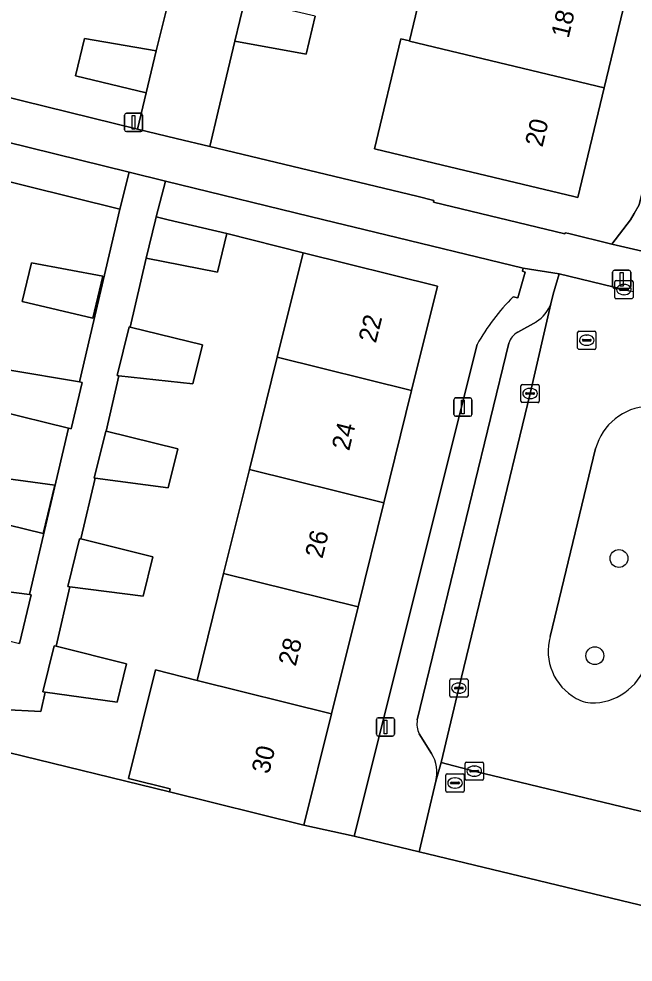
# Model space of a CAD drawing. Extents: x 162803 to 163818, y 381639 to 382475.
# Drawn here: x 163103.1 to 163136.7, y 382209.4 to 382261 of the extents above; entities that cross this region are included whole.
import ezdxf

# ---------------------------------------------------------------- set-up
doc = ezdxf.new("R2010")
doc.units = 0
for name, color, linetype in [('IMGEO_Boom', 7, 'Continuous'), ('IMGEO_Erf', 7, 'Continuous'), ('IMGEO_Groenvoorziening', 7, 'Continuous'), ('IMGEO_Hek', 7, 'Continuous'), ('IMGEO_Kolk', 7, 'Continuous'), ('IMGEO_Lichtmast', 7, 'Continuous'), ('IMGEO_Pand', 7, 'Continuous'), ('IMGEO_Pand_nummerreeks', 7, 'Continuous'), ('IMGEO_Parkeervlak_open', 7, 'Continuous'), ('IMGEO_Rijbaan_lokaal_open', 7, 'Continuous'), ('IMGEO_Rioolput', 7, 'Continuous'), ('IMGEO_Voetpad_open', 7, 'Continuous')]:
    doc.layers.add(name, color=color, linetype=linetype)

msp = doc.modelspace()

# ---------------------------------------------------------------- linework, layer by layer
at = {"layer": 'IMGEO_Boom'}
for centre in [(163135.913, 382231.467), (163134.592, 382226.148)]:
    msp.add_circle(centre, 0.489, dxfattribs=at)
at = {"layer": 'IMGEO_Erf'}
for points in [[(163119.287, 382261.142), (163118.793, 382259.063), (163114.901, 382259.759), (163113.984, 382255.944), (163113.517, 382254.008), (163124.858, 382251.282), (163125.788, 382251.054), (163125.763, 382250.951), (163132.954, 382249.227), (163132.969, 382249.291), (163133.177, 382249.24), (163135.523, 382248.664), (163136.536, 382250), (163136.747, 382250.336), (163137.011, 382250.814), (163151.17, 382309.066)], [(163136.518, 382263.116), (163135.102, 382257.214), (163133.662, 382251.208), (163133.442, 382251.261), (163126.251, 382252.986), (163122.54, 382253.876), (163123.982, 382259.89), (163124.451, 382259.778), (163125.844, 382265.582)], [(163090.662, 382259.598), (163109.57, 382254.957), (163110.032, 382256.941), (163106.177, 382257.866), (163106.669, 382259.919), (163110.582, 382259.234), (163111.502, 382262.908)], [(163102.463, 382241.778), (163106.389, 382241.125), (163108.604, 382250.569), (163100.863, 382252.485)], [(163130.126, 382245.787), (163130.388, 382245.731), (163130.783, 382247.133), (163130.637, 382247.179), (163130.671, 382247.351), (163122.549, 382249.324), (163119.771, 382250), (163111.102, 382252.11), (163110.582, 382250.157), (163111.242, 382250), (163114.449, 382249.237), (163118.626, 382248.182), (163125.984, 382246.357), (163124.569, 382240.655), (163123.046, 382234.515), (163121.633, 382228.819), (163120.183, 382222.974), (163118.671, 382216.877), (163121.429, 382216.275), (163128.151, 382243.17)], [(163093.672, 382223), (163111.314, 382218.702), (163111.353, 382218.859), (163109.073, 382219.425), (163110.546, 382225.365), (163112.826, 382224.799), (163114.276, 382230.644), (163115.689, 382236.341), (163117.212, 382242.481), (163118.626, 382248.182), (163114.449, 382249.237), (163113.948, 382247.127), (163110.043, 382247.894), (163109.168, 382244.13), (163113.115, 382243.151), (163112.586, 382241.016), (163108.548, 382241.464), (163107.843, 382238.433), (163111.768, 382237.46), (163111.239, 382235.329), (163107.244, 382235.858), (163106.471, 382232.532), (163110.405, 382231.555), (163109.87, 382229.401), (163105.862, 382229.913), (163105.106, 382226.662), (163108.968, 382225.704), (163108.448, 382223.605), (163104.522, 382224.152), (163104.275, 382223.089), (163102.186, 382223.204)], [(163099.653, 382229.998), (163103.66, 382229.49), (163105.796, 382238.598), (163101.918, 382239.544)]]:
    msp.add_lwpolyline(points, dxfattribs=at)
for points in [[(163089.618, 382255.32), (163093.508, 382254.28), (163100.863, 382252.485), (163108.604, 382250.569), (163109.113, 382252.594), (163090.093, 382257.281)], [(163107.115, 382244.612), (163103.258, 382245.529), (163103.761, 382247.643), (163107.663, 382246.92)], [(163101.14, 382236.002), (163105.049, 382235.468), (163104.406, 382232.828), (163100.593, 382233.758)], [(163150.047, 382209.293), (163144.013, 382210.786), (163141.809, 382211.34), (163138.535, 382212.15), (163124.973, 382215.424), (163121.429, 382216.275), (163118.671, 382216.877), (163111.314, 382218.702), (163093.672, 382223), (163086.358, 382224.789), (163082.453, 382225.745), (163069.123, 382170.722), (163071.74, 382166.782), (163081.213, 382162.978), (163089.555, 382160.344), (163135.606, 382149.117)]]:
    msp.add_lwpolyline(points, close=True, dxfattribs=at)
msp.add_arc((163138.783, 382237.2), 12.193, 135.2324, 150.6853, dxfattribs=at)
at = {"layer": 'IMGEO_Groenvoorziening'}
msp.add_lwpolyline([(163134.638, 382237.481), (163132.148, 382227.198)], dxfattribs=at)
for centre, radius, start, end in [((163137.644, 382236.677), 3.112, 92.1882, 165.0199), ((163134.995, 382226.402), 2.956, 164.378, 241.2288), ((163134.437, 382226.69), 3.125, 273.367, 345.671), ((163134.471, 382225.329), 1.764, 239.3539, 274.8724)]:
    msp.add_arc(centre, radius, start, end, dxfattribs=at)
at = {"layer": 'IMGEO_Hek'}
for points in [[(163109.57, 382254.957), (163111.675, 382254.451)], [(163118.671, 382216.877), (163121.429, 382216.275)]]:
    msp.add_lwpolyline(points, dxfattribs=at)
at = {"layer": 'IMGEO_Kolk'}
for p, q in [((163135.683, 382245.751), (163135.683, 382246.603)), ((163135.758, 382246.677), (163136.61, 382246.677)), ((163136.171, 382246.457), (163136.196, 382246.457)), ((163136.684, 382246.603), (163136.684, 382245.751)), ((163135.942, 382246.171), (163135.942, 382246.183)), ((163136.38, 382246.134), (163135.982, 382246.134)), ((163135.985, 382246.22), (163136.383, 382246.22)), ((163136.194, 382245.897), (163136.169, 382245.897)), ((163136.426, 382246.183), (163136.426, 382246.171)), ((163136.61, 382245.677), (163135.758, 382245.677)), ((163130.548, 382240.065), (163130.548, 382240.917)), ((163130.623, 382240.991), (163131.475, 382240.991)), ((163131.036, 382240.771), (163131.061, 382240.771)), ((163131.549, 382240.917), (163131.549, 382240.065)), ((163130.807, 382240.485), (163130.807, 382240.497)), ((163131.245, 382240.448), (163130.847, 382240.448)), ((163130.85, 382240.534), (163131.248, 382240.534)), ((163131.059, 382240.211), (163131.034, 382240.211)), ((163131.291, 382240.497), (163131.291, 382240.485)), ((163131.475, 382239.991), (163130.623, 382239.991)), ((163126.652, 382223.948), (163126.652, 382224.8)), ((163126.727, 382224.874), (163127.579, 382224.874)), ((163127.653, 382224.8), (163127.653, 382223.948)), ((163126.911, 382224.368), (163126.911, 382224.38)), ((163127.349, 382224.331), (163126.951, 382224.331)), ((163126.954, 382224.417), (163127.352, 382224.417)), ((163127.14, 382224.654), (163127.165, 382224.654)), ((163127.395, 382224.38), (163127.395, 382224.368)), ((163127.579, 382223.874), (163126.727, 382223.874)), ((163127.163, 382224.094), (163127.138, 382224.094)), ((163127.495, 382219.405), (163127.495, 382220.257)), ((163127.57, 382220.331), (163128.422, 382220.331)), ((163127.983, 382220.111), (163128.008, 382220.111)), ((163128.496, 382220.257), (163128.496, 382219.405)), ((163127.754, 382219.825), (163127.754, 382219.837)), ((163128.192, 382219.788), (163127.794, 382219.788)), ((163127.797, 382219.874), (163128.195, 382219.874)), ((163128.006, 382219.551), (163127.981, 382219.551)), ((163128.238, 382219.837), (163128.238, 382219.825)), ((163128.422, 382219.331), (163127.57, 382219.331))]:
    msp.add_line(p, q, dxfattribs=at)
for points in [[(163135.683, 382245.751), (163135.683, 382246.603)], [(163135.758, 382246.677), (163136.61, 382246.677)], [(163136.684, 382246.603), (163136.684, 382245.751)], [(163136.61, 382245.677), (163135.758, 382245.677)], [(163130.548, 382240.065), (163130.548, 382240.917)], [(163130.623, 382240.991), (163131.475, 382240.991)], [(163131.549, 382240.917), (163131.549, 382240.065)], [(163131.475, 382239.991), (163130.623, 382239.991)], [(163126.652, 382223.948), (163126.652, 382224.8)], [(163126.727, 382224.874), (163127.579, 382224.874)], [(163127.653, 382224.8), (163127.653, 382223.948)], [(163127.579, 382223.874), (163126.727, 382223.874)], [(163127.495, 382219.405), (163127.495, 382220.257)], [(163127.57, 382220.331), (163128.422, 382220.331)], [(163128.496, 382220.257), (163128.496, 382219.405)], [(163128.422, 382219.331), (163127.57, 382219.331)]]:
    msp.add_lwpolyline(points, dxfattribs=at)
for centre, radius, start, end in [((163135.76, 382246.601), 0.0765, 91.552, 178.448), ((163135.76, 382246.601), 0.0765, 91.552, 178.448), ((163136.608, 382246.601), 0.0765, 1.552, 88.448), ((163136.608, 382246.601), 0.0765, 1.552, 88.448), ((163135.982, 382246.18), 0.0403, 85.8775, 175.7526), ((163135.979, 382246.17), 0.0366, 178.938, 274.7102), ((163136.383, 382246.177), 0.043, 264.8664, 352.4533), ((163136.387, 382246.182), 0.0386, 1.7309, 96.639), ((163135.76, 382245.753), 0.0765, 181.552, 268.448), ((163135.76, 382245.753), 0.0765, 181.552, 268.448), ((163136.608, 382245.753), 0.0765, 271.552, 358.448), ((163136.608, 382245.753), 0.0765, 271.552, 358.448), ((163130.625, 382240.915), 0.0765, 91.552, 178.448), ((163130.625, 382240.915), 0.0765, 91.552, 178.448), ((163131.473, 382240.915), 0.0765, 1.552, 88.448), ((163131.473, 382240.915), 0.0765, 1.552, 88.448), ((163130.847, 382240.494), 0.0403, 85.8775, 175.7526), ((163130.844, 382240.484), 0.0366, 178.938, 274.7102), ((163131.248, 382240.491), 0.043, 264.8664, 352.4533), ((163131.252, 382240.496), 0.0386, 1.7309, 96.639), ((163130.625, 382240.067), 0.0765, 181.552, 268.448), ((163130.625, 382240.067), 0.0765, 181.552, 268.448), ((163131.473, 382240.067), 0.0765, 271.552, 358.448), ((163131.473, 382240.067), 0.0765, 271.552, 358.448), ((163126.729, 382224.798), 0.0765, 91.552, 178.448), ((163126.729, 382224.798), 0.0765, 91.552, 178.448), ((163127.577, 382224.798), 0.0765, 1.552, 88.448), ((163127.577, 382224.798), 0.0765, 1.552, 88.448), ((163126.951, 382224.377), 0.0403, 85.8775, 175.7526), ((163126.948, 382224.367), 0.0366, 178.938, 274.7102), ((163127.352, 382224.374), 0.043, 264.8664, 352.4533), ((163127.356, 382224.379), 0.0386, 1.7309, 96.639), ((163126.729, 382223.95), 0.0765, 181.552, 268.448), ((163126.729, 382223.95), 0.0765, 181.552, 268.448), ((163127.577, 382223.95), 0.0765, 271.552, 358.448), ((163127.577, 382223.95), 0.0765, 271.552, 358.448), ((163127.572, 382220.255), 0.0765, 91.552, 178.448), ((163127.572, 382220.255), 0.0765, 91.552, 178.448), ((163128.42, 382220.255), 0.0765, 1.552, 88.448), ((163128.42, 382220.255), 0.0765, 1.552, 88.448), ((163127.794, 382219.834), 0.0403, 85.8775, 175.7526), ((163127.791, 382219.824), 0.0366, 178.938, 274.7102), ((163128.195, 382219.831), 0.043, 264.8664, 352.4533), ((163128.199, 382219.836), 0.0386, 1.7309, 96.639), ((163127.572, 382219.407), 0.0765, 181.552, 268.448), ((163127.572, 382219.407), 0.0765, 181.552, 268.448), ((163128.42, 382219.407), 0.0765, 271.552, 358.448), ((163128.42, 382219.407), 0.0765, 271.552, 358.448)]:
    msp.add_arc(centre, radius, start, end, dxfattribs=at)
for centre, major_axis, ratio, start_param, end_param in [((163136.17, 382246.177), (-0.387, 0.002), 0.722429, 4.712389, 7.853982), ((163136.195, 382246.177), (-0.39, 0.002), 0.717154, 1.570796, 4.712389), ((163131.035, 382240.491), (-0.387, 0.002), 0.722429, 4.712389, 7.853982), ((163131.06, 382240.491), (-0.39, 0.002), 0.717154, 1.570796, 4.712389), ((163127.139, 382224.374), (-0.387, 0.002), 0.722429, 4.712389, 7.853982), ((163127.164, 382224.374), (-0.39, 0.002), 0.717154, 1.570796, 4.712389), ((163127.982, 382219.831), (-0.387, 0.002), 0.722429, 4.712389, 7.853982), ((163128.007, 382219.831), (-0.39, 0.002), 0.717154, 1.570796, 4.712389)]:
    msp.add_ellipse(centre, major_axis=major_axis, ratio=ratio, start_param=start_param, end_param=end_param, dxfattribs=at)
at = {"layer": 'IMGEO_Lichtmast'}
for p, q in [((163108.856, 382254.921), (163108.856, 382255.721)), ((163108.856, 382255.721), (163108.856, 382254.921)), ((163108.956, 382255.821), (163109.746, 382255.821)), ((163109.746, 382255.821), (163108.956, 382255.821)), ((163109.846, 382255.721), (163109.846, 382254.921)), ((163109.846, 382254.921), (163109.846, 382255.721)), ((163109.746, 382254.821), (163108.956, 382254.821)), ((163108.956, 382254.821), (163109.746, 382254.821)), ((163135.565, 382246.337), (163135.565, 382247.137)), ((163135.565, 382247.137), (163135.565, 382246.337)), ((163135.665, 382247.237), (163136.455, 382247.237)), ((163136.455, 382247.237), (163135.665, 382247.237)), ((163136.555, 382247.137), (163136.555, 382246.337)), ((163136.555, 382246.337), (163136.555, 382247.137)), ((163136.455, 382246.237), (163135.665, 382246.237)), ((163135.665, 382246.237), (163136.455, 382246.237)), ((163126.976, 382240.246), (163127.766, 382240.246)), ((163127.766, 382240.246), (163126.976, 382240.246)), ((163126.876, 382239.346), (163126.876, 382240.146)), ((163126.876, 382240.146), (163126.876, 382239.346)), ((163127.866, 382240.146), (163127.866, 382239.346)), ((163127.866, 382239.346), (163127.866, 382240.146)), ((163127.766, 382239.246), (163126.976, 382239.246)), ((163126.976, 382239.246), (163127.766, 382239.246)), ((163122.637, 382221.852), (163122.637, 382222.652)), ((163122.637, 382222.652), (163122.637, 382221.852)), ((163122.737, 382222.752), (163123.527, 382222.752)), ((163123.527, 382222.752), (163122.737, 382222.752)), ((163123.627, 382222.652), (163123.627, 382221.852)), ((163123.627, 382221.852), (163123.627, 382222.652)), ((163123.527, 382221.752), (163122.737, 382221.752)), ((163122.737, 382221.752), (163123.527, 382221.752))]:
    msp.add_line(p, q, dxfattribs=at)
for points in [[(163109.276, 382255.696), (163109.426, 382255.696), (163109.426, 382254.946), (163109.276, 382254.946), (163109.276, 382255.696)], [(163135.985, 382247.112), (163136.135, 382247.112), (163136.135, 382246.362), (163135.985, 382246.362), (163135.985, 382247.112)], [(163127.296, 382240.121), (163127.446, 382240.121), (163127.446, 382239.371), (163127.296, 382239.371), (163127.296, 382240.121)], [(163123.057, 382222.627), (163123.207, 382222.627), (163123.207, 382221.877), (163123.057, 382221.877), (163123.057, 382222.627)]]:
    msp.add_lwpolyline(points, dxfattribs=at)
for centre, start, end in [((163108.956, 382255.721), 90, 180), ((163108.956, 382255.721), 90, 180), ((163109.746, 382255.721), 0, 90), ((163109.746, 382255.721), 360, 90), ((163108.956, 382254.921), 180, 270), ((163108.956, 382254.921), 180, 270), ((163109.746, 382254.921), 270, 0), ((163109.746, 382254.921), 270, 0), ((163135.665, 382247.137), 90, 180), ((163135.665, 382247.137), 90, 180), ((163136.455, 382247.137), 0, 90), ((163136.455, 382247.137), 360, 90), ((163135.665, 382246.337), 180, 270), ((163135.665, 382246.337), 180, 270), ((163136.455, 382246.337), 270, 0), ((163136.455, 382246.337), 270, 0), ((163126.976, 382240.146), 90, 180), ((163126.976, 382240.146), 90, 180), ((163127.766, 382240.146), 0, 90), ((163127.766, 382240.146), 360, 90), ((163126.976, 382239.346), 180, 270), ((163126.976, 382239.346), 180, 270), ((163127.766, 382239.346), 270, 0), ((163127.766, 382239.346), 270, 0), ((163122.737, 382222.652), 90, 180), ((163122.737, 382222.652), 90, 180), ((163123.527, 382222.652), 0, 90), ((163123.527, 382222.652), 360, 90), ((163122.737, 382221.852), 180, 270), ((163122.737, 382221.852), 180, 270), ((163123.527, 382221.852), 270, 0), ((163123.527, 382221.852), 270, 0)]:
    msp.add_arc(centre, 0.1, start, end, dxfattribs=at)
at = {"layer": 'IMGEO_Pand'}
for points in [[(163136.518, 382263.116), (163129.107, 382264.894), (163129.085, 382264.804), (163125.844, 382265.582), (163124.451, 382259.778), (163124.449, 382259.77), (163135.102, 382257.214)], [(163118.793, 382259.063), (163119.287, 382261.142), (163115.447, 382262.055), (163114.901, 382259.759)], [(163110.032, 382256.941), (163110.582, 382259.234), (163106.669, 382259.919), (163106.177, 382257.866)], [(163135.102, 382257.214), (163124.449, 382259.77), (163124.451, 382259.778), (163123.982, 382259.89), (163122.54, 382253.876), (163126.251, 382252.986), (163133.442, 382251.261), (163133.662, 382251.208)], [(163114.449, 382249.237), (163111.242, 382250), (163110.582, 382250.157), (163110.545, 382250), (163110.043, 382247.894), (163113.948, 382247.127)], [(163117.212, 382242.481), (163124.569, 382240.655), (163125.984, 382246.357), (163118.626, 382248.182)], [(163107.115, 382244.612), (163107.663, 382246.92), (163103.761, 382247.643), (163103.258, 382245.529)], [(163109.168, 382244.13), (163109.117, 382244.143), (163108.455, 382241.474), (163108.548, 382241.464), (163112.586, 382241.016), (163113.115, 382243.151)], [(163117.212, 382242.481), (163115.689, 382236.341), (163123.046, 382234.515), (163124.569, 382240.655)], [(163106.389, 382241.125), (163102.463, 382241.778), (163101.918, 382239.544), (163105.796, 382238.598), (163105.928, 382238.566), (163106.546, 382241.099)], [(163107.843, 382238.433), (163107.832, 382238.436), (163107.194, 382235.865), (163107.244, 382235.858), (163111.239, 382235.329), (163111.768, 382237.46)], [(163114.276, 382230.644), (163121.633, 382228.819), (163123.046, 382234.515), (163115.689, 382236.341)], [(163101.14, 382236.002), (163100.593, 382233.758), (163104.406, 382232.828), (163105.049, 382235.468)], [(163106.471, 382232.532), (163106.401, 382232.549), (163105.751, 382229.927), (163105.862, 382229.913), (163109.87, 382229.401), (163110.405, 382231.555)], [(163114.276, 382230.644), (163112.826, 382224.799), (163120.183, 382222.974), (163121.633, 382228.819)], [(163103.66, 382229.49), (163099.653, 382229.998), (163099.115, 382227.792), (163103.038, 382226.835), (163103.1, 382226.82), (163103.748, 382229.479)], [(163105.106, 382226.662), (163105.014, 382226.685), (163104.39, 382224.17), (163104.522, 382224.152), (163108.448, 382223.605), (163108.968, 382225.704)], [(163120.183, 382222.974), (163112.826, 382224.799), (163110.546, 382225.365), (163109.073, 382219.425), (163111.353, 382218.859), (163111.314, 382218.702), (163118.671, 382216.877)]]:
    msp.add_lwpolyline(points, close=True, dxfattribs=at)
at = {"layer": 'IMGEO_Parkeervlak_open'}
for points in [[(163125.897, 382219.282), (163126.177, 382220.3), (163127.154, 382224.374), (163131.05, 382240.49), (163132.188, 382245.406)], [(163131.394, 382244.422), (163130.38, 382243.842)], [(163129.89, 382243.252), (163124.878, 382222.632)], [(163145.726, 382242.413), (163144.32, 382236.804), (163140.443, 382220.841), (163139.498, 382217.076), (163137.595, 382217.507), (163127.997, 382219.832), (163126.177, 382220.3), (163125.897, 382219.282), (163124.973, 382215.424), (163138.535, 382212.15), (163139.43, 382215.984)], [(163124.984, 382221.872), (163125.654, 382220.8)]]:
    msp.add_lwpolyline(points, dxfattribs=at)
for centre, radius, start, end in [((163130.279, 382246.134), 2.043, 303.0758, 339.1234), ((163130.829, 382242.97), 0.98, 117.2659, 163.3143), ((163126.009, 382222.402), 1.154, 168.5294, 207.3507), ((163123.987, 382219.755), 1.968, 346.0997, 32.0897)]:
    msp.add_arc(centre, radius, start, end, dxfattribs=at)
at = {"layer": 'IMGEO_Rijbaan_lokaal_open'}
for points in [[(163136.382, 382246.138), (163136.184, 382246.175), (163132.637, 382247.045), (163132.31, 382245.931), (163132.188, 382245.406), (163131.05, 382240.49), (163127.154, 382224.374), (163126.177, 382220.3), (163127.997, 382219.832), (163137.595, 382217.507), (163139.498, 382217.076), (163140.443, 382220.841), (163144.32, 382236.804), (163145.726, 382242.413)], [(163132.148, 382227.198), (163134.638, 382237.481)]]:
    msp.add_lwpolyline(points, dxfattribs=at)
for centre, radius, start, end in [((163136.919, 382247.993), 1.931, 253.8567, 263.3116), ((163137.644, 382236.677), 3.112, 92.1882, 165.0199), ((163134.995, 382226.402), 2.956, 164.378, 241.2288), ((163134.437, 382226.69), 3.125, 273.367, 345.671), ((163134.471, 382225.329), 1.764, 239.3539, 274.8724)]:
    msp.add_arc(centre, radius, start, end, dxfattribs=at)
at = {"layer": 'IMGEO_Rioolput'}
for p, q in [((163133.65, 382242.981), (163133.65, 382243.833)), ((163133.725, 382243.907), (163134.577, 382243.907)), ((163134.651, 382243.833), (163134.651, 382242.981)), ((163133.909, 382243.401), (163133.909, 382243.413)), ((163134.347, 382243.364), (163133.949, 382243.364)), ((163133.952, 382243.45), (163134.35, 382243.45)), ((163134.138, 382243.687), (163134.163, 382243.687)), ((163134.393, 382243.413), (163134.393, 382243.401)), ((163134.577, 382242.907), (163133.725, 382242.907)), ((163134.161, 382243.127), (163134.136, 382243.127)), ((163126.441, 382218.757), (163126.441, 382219.609)), ((163126.516, 382219.683), (163127.368, 382219.683)), ((163127.442, 382219.609), (163127.442, 382218.757)), ((163126.7, 382219.177), (163126.7, 382219.189)), ((163127.138, 382219.14), (163126.74, 382219.14)), ((163126.743, 382219.226), (163127.141, 382219.226)), ((163126.929, 382219.463), (163126.954, 382219.463)), ((163127.184, 382219.189), (163127.184, 382219.177)), ((163127.368, 382218.683), (163126.516, 382218.683)), ((163126.952, 382218.903), (163126.927, 382218.903))]:
    msp.add_line(p, q, dxfattribs=at)
for points in [[(163133.65, 382242.981), (163133.65, 382243.833)], [(163133.725, 382243.907), (163134.577, 382243.907)], [(163134.651, 382243.833), (163134.651, 382242.981)], [(163134.577, 382242.907), (163133.725, 382242.907)], [(163126.441, 382218.757), (163126.441, 382219.609)], [(163126.516, 382219.683), (163127.368, 382219.683)], [(163127.442, 382219.609), (163127.442, 382218.757)], [(163127.368, 382218.683), (163126.516, 382218.683)]]:
    msp.add_lwpolyline(points, dxfattribs=at)
for centre, radius, start, end in [((163133.727, 382243.831), 0.0765, 91.552, 178.448), ((163133.727, 382243.831), 0.0765, 91.552, 178.448), ((163134.575, 382243.831), 0.0765, 1.552, 88.448), ((163134.575, 382243.831), 0.0765, 1.552, 88.448), ((163133.949, 382243.41), 0.0403, 85.8775, 175.7526), ((163133.946, 382243.4), 0.0366, 178.938, 274.7102), ((163134.35, 382243.407), 0.043, 264.8664, 352.4533), ((163134.354, 382243.412), 0.0386, 1.7309, 96.639), ((163133.727, 382242.983), 0.0765, 181.552, 268.448), ((163133.727, 382242.983), 0.0765, 181.552, 268.448), ((163134.575, 382242.983), 0.0765, 271.552, 358.448), ((163134.575, 382242.983), 0.0765, 271.552, 358.448), ((163126.518, 382219.607), 0.0765, 91.552, 178.448), ((163126.518, 382219.607), 0.0765, 91.552, 178.448), ((163127.366, 382219.607), 0.0765, 1.552, 88.448), ((163127.366, 382219.607), 0.0765, 1.552, 88.448), ((163126.74, 382219.186), 0.0403, 85.8775, 175.7526), ((163126.737, 382219.176), 0.0366, 178.938, 274.7102), ((163127.141, 382219.183), 0.043, 264.8664, 352.4533), ((163127.145, 382219.188), 0.0386, 1.7309, 96.639), ((163126.518, 382218.759), 0.0765, 181.552, 268.448), ((163126.518, 382218.759), 0.0765, 181.552, 268.448), ((163127.366, 382218.759), 0.0765, 271.552, 358.448), ((163127.366, 382218.759), 0.0765, 271.552, 358.448)]:
    msp.add_arc(centre, radius, start, end, dxfattribs=at)
for centre, major_axis, ratio, start_param, end_param in [((163134.137, 382243.407), (-0.387, 0.002), 0.722429, 4.712389, 7.853982), ((163134.162, 382243.407), (-0.39, 0.002), 0.717154, 1.570796, 4.712389), ((163126.928, 382219.183), (-0.387, 0.002), 0.722429, 4.712389, 7.853982), ((163126.953, 382219.183), (-0.39, 0.002), 0.717154, 1.570796, 4.712389)]:
    msp.add_ellipse(centre, major_axis=major_axis, ratio=ratio, start_param=start_param, end_param=end_param, dxfattribs=at)
at = {"layer": 'IMGEO_Voetpad_open'}
for points in [[(163157.986, 382325.467), (163158.84, 382329.032), (163156.205, 382329.677), (163155.006, 382324.801), (163150.02, 382326.027), (163151.219, 382330.903), (163150.106, 382331.192), (163149.794, 382329.806), (163147.979, 382322.337), (163146.18, 382315.122), (163145.582, 382312.628), (163145.083, 382310.543), (163147.739, 382309.906), (163151.17, 382309.066), (163137.011, 382250.814), (163136.747, 382250.336), (163136.536, 382250), (163135.523, 382248.664), (163139.012, 382247.86)], [(163113.517, 382254.008), (163111.675, 382254.451), (163109.57, 382254.957), (163090.662, 382259.598), (163090.093, 382257.281), (163109.113, 382252.594), (163111.102, 382252.11), (163119.771, 382250), (163122.549, 382249.324), (163130.671, 382247.351), (163132.637, 382247.045), (163136.184, 382246.175), (163136.382, 382246.138)], [(163139.012, 382247.86), (163135.523, 382248.664), (163133.177, 382249.24), (163132.969, 382249.291), (163132.954, 382249.227), (163125.763, 382250.951), (163125.788, 382251.054), (163124.858, 382251.282), (163113.517, 382254.008)], [(163102.186, 382223.204), (163104.275, 382223.089), (163104.522, 382224.152), (163104.39, 382224.17), (163105.014, 382226.685), (163105.106, 382226.662), (163105.862, 382229.913), (163105.751, 382229.927), (163106.401, 382232.549), (163106.471, 382232.532), (163107.244, 382235.858), (163107.194, 382235.865), (163107.832, 382238.436), (163107.843, 382238.433), (163108.548, 382241.464), (163108.455, 382241.474), (163109.117, 382244.143), (163109.168, 382244.13), (163110.043, 382247.894), (163110.545, 382250), (163110.582, 382250.157), (163111.102, 382252.11), (163109.113, 382252.594), (163108.604, 382250.569), (163106.389, 382241.125), (163106.546, 382241.099), (163105.928, 382238.566), (163105.796, 382238.598), (163103.66, 382229.49), (163103.748, 382229.479), (163103.1, 382226.82), (163103.038, 382226.835)], [(163132.188, 382245.406), (163132.31, 382245.931), (163132.637, 382247.045), (163130.671, 382247.351), (163130.637, 382247.179), (163130.783, 382247.133), (163130.388, 382245.731), (163130.126, 382245.787)], [(163130.38, 382243.842), (163131.394, 382244.422)], [(163128.151, 382243.17), (163121.429, 382216.275), (163124.973, 382215.424), (163125.897, 382219.282)], [(163124.878, 382222.632), (163129.89, 382243.252)], [(163125.654, 382220.8), (163124.984, 382221.872)]]:
    msp.add_lwpolyline(points, dxfattribs=at)
msp.add_lwpolyline([(163120.656, 382282.865), (163116.747, 382283.844), (163115.012, 382276.917), (163115.168, 382276.893), (163114.562, 382274.397), (163114.391, 382274.439), (163113.547, 382271.07), (163113.86, 382271.017), (163113.254, 382268.521), (163112.928, 382268.6), (163112.083, 382265.224), (163112.354, 382265.182), (163111.785, 382262.839), (163111.502, 382262.908), (163110.582, 382259.234), (163110.032, 382256.941), (163109.57, 382254.957), (163111.675, 382254.451), (163113.517, 382254.008), (163113.984, 382255.944), (163114.901, 382259.759), (163115.447, 382262.055)], close=True, dxfattribs=at)
for centre, radius, start, end in [((163136.919, 382247.993), 1.931, 253.8567, 263.3116), ((163138.783, 382237.2), 12.193, 135.2324, 150.6853), ((163130.279, 382246.134), 2.043, 303.0758, 339.1234), ((163130.829, 382242.97), 0.98, 117.2659, 163.3143), ((163126.009, 382222.402), 1.154, 168.5294, 207.3507), ((163123.987, 382219.755), 1.968, 346.0997, 32.0897)]:
    msp.add_arc(centre, radius, start, end, dxfattribs=at)

# ---------------------------------------------------------------- texts
at = {"layer": 'IMGEO_Pand_nummerreeks'}
for s, rotation, p in [('18', 76.5128, (163133.153, 382259.888)), ('20', 76.5128, (163131.724, 382253.93)), ('22', 76.0681, (163122.607, 382243.211)), ('24', 76.0681, (163121.145, 382237.318)), ('26', 76.0681, (163119.683, 382231.422)), ('28', 76.0681, (163118.22, 382225.529)), ('30', 76.0681, (163116.758, 382219.633))]:
    msp.add_text(s, height=1, rotation=rotation, dxfattribs=at).set_placement(p)

doc.saveas('drawing.dxf')
